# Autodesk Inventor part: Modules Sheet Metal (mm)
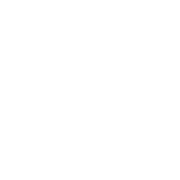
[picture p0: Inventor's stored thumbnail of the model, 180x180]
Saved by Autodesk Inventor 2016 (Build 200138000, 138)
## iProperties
Created: 2014-08
Part Number: Modules Sheet Metal (mm)
Material: Generic
Document SubType Name: Sheet Metal
Designer: Wally
Density: 1 g/cm^3
Sheet Metal Rule: Default
Appearance: Default
Author: Wally
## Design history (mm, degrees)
node "Sketch1"
other parameters: "Thickness" = 0.5, "BendRadius" = 0.5 (= Thickness), "BendReliefWidth" = 0.5 (= Thickness), "BendReliefDepth" = 0.25 (= 0.5 x Thickness), "CornerReliefSize" = 2 (= 4 x Thickness), "SeamGap" = 0.01, "MinimumRemnant" = 1 (= 2 x Thickness), "TransitionRadius" = 0.5 (= BendRadius), "JacobiRadiusSize" = 0.5 (= BendRadius), "GapSize" = 0.5 (= Thickness)
